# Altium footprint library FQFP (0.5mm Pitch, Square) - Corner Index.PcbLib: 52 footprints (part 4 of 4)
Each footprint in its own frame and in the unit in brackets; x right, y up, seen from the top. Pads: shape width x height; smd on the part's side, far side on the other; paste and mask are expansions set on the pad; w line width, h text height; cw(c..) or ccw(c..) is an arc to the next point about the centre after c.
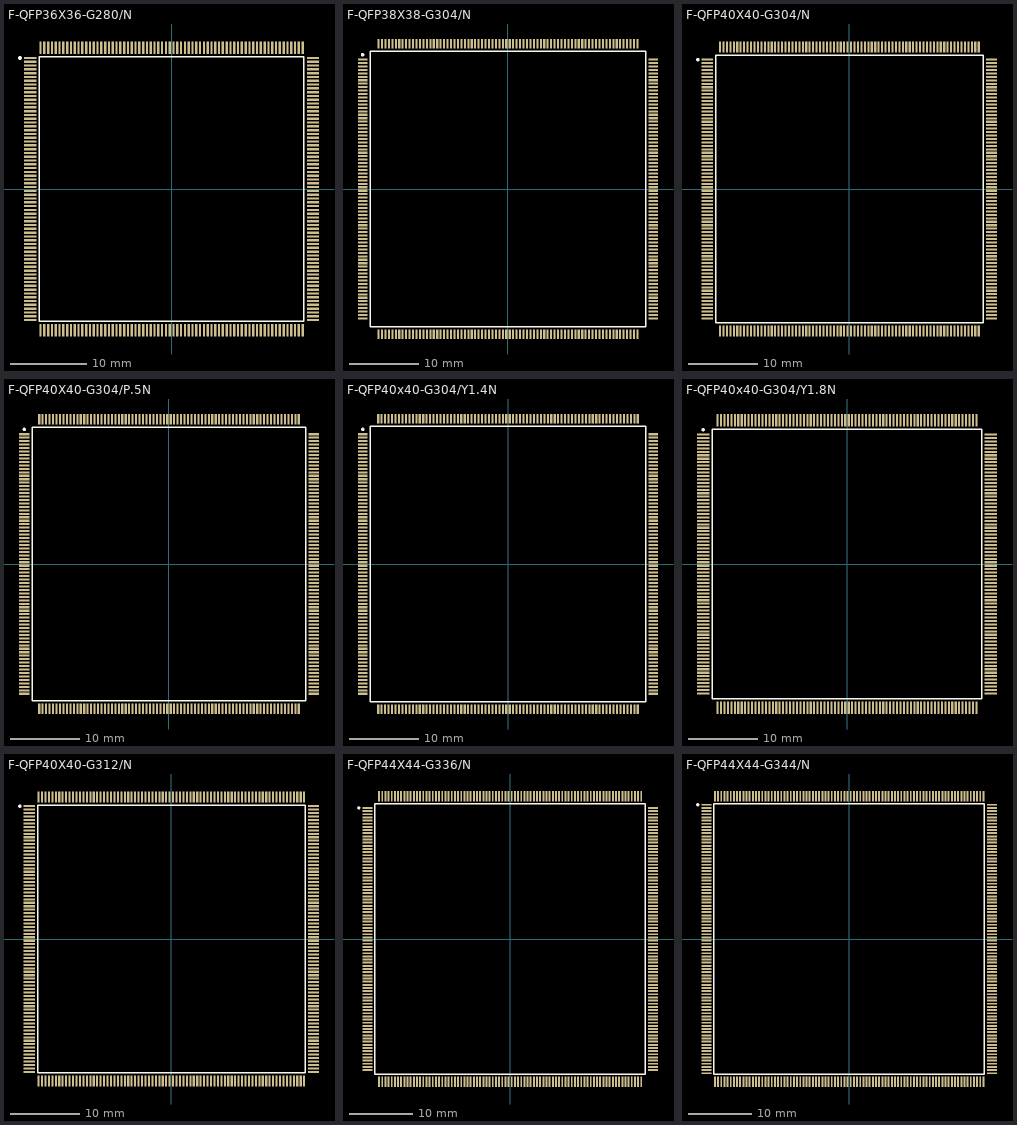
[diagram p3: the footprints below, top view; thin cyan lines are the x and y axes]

## F-QFP36X36-G280/N [mm]
pads (280):
  rect 1.6x0.3 smd: 1(-18.6,17.25) 2(-18.6,16.75) 3(-18.6,16.25) 4(-18.6,15.75) 5(-18.6,15.25) 6(-18.6,14.75) 7(-18.6,14.25) 8(-18.6,13.75) 9(-18.6,13.25) 10(-18.6,12.75) 11(-18.6,12.25) 12(-18.6,11.75) 13(-18.6,11.25) 14(-18.6,10.75) 15(-18.6,10.25) 16(-18.6,9.75) 17(-18.6,9.25) 18(-18.6,8.75) 19(-18.6,8.25) 20(-18.6,7.75) 21(-18.6,7.25) 22(-18.6,6.75) 23(-18.6,6.25) 24(-18.6,5.75) 25(-18.6,5.25) 26(-18.6,4.75) 27(-18.6,4.25) 28(-18.6,3.75) 29(-18.6,3.25) 30(-18.6,2.75) 31(-18.6,2.25) 32(-18.6,1.75) 33(-18.6,1.25) 34(-18.6,0.75) 35(-18.6,0.25) 36(-18.6,-0.25) 37(-18.6,-0.75) 38(-18.6,-1.25) 39(-18.6,-1.75) 40(-18.6,-2.25) 41(-18.6,-2.75) 42(-18.6,-3.25) 43(-18.6,-3.75) 44(-18.6,-4.25) 45(-18.6,-4.75) 46(-18.6,-5.25) 47(-18.6,-5.75) 48(-18.6,-6.25) 49(-18.6,-6.75) 50(-18.6,-7.25) 51(-18.6,-7.75) 52(-18.6,-8.25) 53(-18.6,-8.75) 54(-18.6,-9.25) 55(-18.6,-9.75) 56(-18.6,-10.25) 57(-18.6,-10.75) 58(-18.6,-11.25) 59(-18.6,-11.75) 60(-18.6,-12.25) 61(-18.6,-12.75) 62(-18.6,-13.25) 63(-18.6,-13.75) 64(-18.6,-14.25) 65(-18.6,-14.75) 66(-18.6,-15.25) 67(-18.6,-15.75) 68(-18.6,-16.25) 69(-18.6,-16.75) 70(-18.6,-17.25) 141(18.6,-17.25) 142(18.6,-16.75) 143(18.6,-16.25) 144(18.6,-15.75) 145(18.6,-15.25) 146(18.6,-14.75) 147(18.6,-14.25) 148(18.6,-13.75) 149(18.6,-13.25) 150(18.6,-12.75) 151(18.6,-12.25) 152(18.6,-11.75) 153(18.6,-11.25) 154(18.6,-10.75) 155(18.6,-10.25) 156(18.6,-9.75) 157(18.6,-9.25) 158(18.6,-8.75) 159(18.6,-8.25) 160(18.6,-7.75) 161(18.6,-7.25) 162(18.6,-6.75) 163(18.6,-6.25) 164(18.6,-5.75) 165(18.6,-5.25) 166(18.6,-4.75) 167(18.6,-4.25) 168(18.6,-3.75) 169(18.6,-3.25) 170(18.6,-2.75) 171(18.6,-2.25) 172(18.6,-1.75) 173(18.6,-1.25) 174(18.6,-0.75) 175(18.6,-0.25) 176(18.6,0.25) 177(18.6,0.75) 178(18.6,1.25) 179(18.6,1.75) 180(18.6,2.25) 181(18.6,2.75) 182(18.6,3.25) 183(18.6,3.75) 184(18.6,4.25) 185(18.6,4.75) 186(18.6,5.25) 187(18.6,5.75) 188(18.6,6.25) 189(18.6,6.75) 190(18.6,7.25) 191(18.6,7.75) 192(18.6,8.25) 193(18.6,8.75) 194(18.6,9.25) 195(18.6,9.75) 196(18.6,10.25) 197(18.6,10.75) 198(18.6,11.25) 199(18.6,11.75) 200(18.6,12.25) 201(18.6,12.75) 202(18.6,13.25) 203(18.6,13.75) 204(18.6,14.25) 205(18.6,14.75) 206(18.6,15.25) 207(18.6,15.75) 208(18.6,16.25) 209(18.6,16.75) 210(18.6,17.25)
  rect 0.3x1.6 smd: 71(-17.25,-18.6) 72(-16.75,-18.6) 73(-16.25,-18.6) 74(-15.75,-18.6) 75(-15.25,-18.6) 76(-14.75,-18.6) 77(-14.25,-18.6) 78(-13.75,-18.6) 79(-13.25,-18.6) 80(-12.75,-18.6) 81(-12.25,-18.6) 82(-11.75,-18.6) 83(-11.25,-18.6) 84(-10.75,-18.6) 85(-10.25,-18.6) 86(-9.75,-18.6) 87(-9.25,-18.6) 88(-8.75,-18.6) 89(-8.25,-18.6) 90(-7.75,-18.6) 91(-7.25,-18.6) 92(-6.75,-18.6) 93(-6.25,-18.6) 94(-5.75,-18.6) 95(-5.25,-18.6) 96(-4.75,-18.6) 97(-4.25,-18.6) 98(-3.75,-18.6) 99(-3.25,-18.6) 100(-2.75,-18.6) 101(-2.25,-18.6) 102(-1.75,-18.6) 103(-1.25,-18.6) 104(-0.75,-18.6) 105(-0.25,-18.6) 106(0.25,-18.6) 107(0.75,-18.6) 108(1.25,-18.6) 109(1.75,-18.6) 110(2.25,-18.6) 111(2.75,-18.6) 112(3.25,-18.6) 113(3.75,-18.6) 114(4.25,-18.6) 115(4.75,-18.6) 116(5.25,-18.6) 117(5.75,-18.6) 118(6.25,-18.6) 119(6.75,-18.6) 120(7.25,-18.6) 121(7.75,-18.6) 122(8.25,-18.6) 123(8.75,-18.6) 124(9.25,-18.6) 125(9.75,-18.6) 126(10.25,-18.6) 127(10.75,-18.6) 128(11.25,-18.6) 129(11.75,-18.6) 130(12.25,-18.6) 131(12.75,-18.6) 132(13.25,-18.6) 133(13.75,-18.6) 134(14.25,-18.6) 135(14.75,-18.6) 136(15.25,-18.6) 137(15.75,-18.6) 138(16.25,-18.6) 139(16.75,-18.6) 140(17.25,-18.6) 211(17.25,18.6) 212(16.75,18.6) 213(16.25,18.6) 214(15.75,18.6) 215(15.25,18.6) 216(14.75,18.6) 217(14.25,18.6) 218(13.75,18.6) 219(13.25,18.6) 220(12.75,18.6) 221(12.25,18.6) 222(11.75,18.6) 223(11.25,18.6) 224(10.75,18.6) 225(10.25,18.6) 226(9.75,18.6) 227(9.25,18.6) 228(8.75,18.6) 229(8.25,18.6) 230(7.75,18.6) 231(7.25,18.6) 232(6.75,18.6) 233(6.25,18.6) 234(5.75,18.6) 235(5.25,18.6) 236(4.75,18.6) 237(4.25,18.6) 238(3.75,18.6) 239(3.25,18.6) 240(2.75,18.6) 241(2.25,18.6) 242(1.75,18.6) 243(1.25,18.6) 244(0.75,18.6) 245(0.25,18.6) 246(-0.25,18.6) 247(-0.75,18.6) 248(-1.25,18.6) 249(-1.75,18.6) 250(-2.25,18.6) 251(-2.75,18.6) 252(-3.25,18.6) 253(-3.75,18.6) 254(-4.25,18.6) 255(-4.75,18.6) 256(-5.25,18.6) 257(-5.75,18.6) 258(-6.25,18.6) 259(-6.75,18.6) 260(-7.25,18.6) 261(-7.75,18.6) 262(-8.25,18.6) 263(-8.75,18.6) 264(-9.25,18.6) 265(-9.75,18.6) 266(-10.25,18.6) 267(-10.75,18.6) 268(-11.25,18.6) 269(-11.75,18.6) 270(-12.25,18.6) 271(-12.75,18.6) 272(-13.25,18.6) 273(-13.75,18.6) 274(-14.25,18.6) 275(-14.75,18.6) 276(-15.25,18.6) 277(-15.75,18.6) 278(-16.25,18.6) 279(-16.75,18.6) 280(-17.25,18.6)
Top Overlay:
  circle w0.25: c-19.96,17.25 r0.125
  lines w0.2: -17.4,-17.4 17.4,-17.4 17.4,17.4 -17.4,17.4 -17.4,-17.4

## F-QFP38X38-G304/N [mm]
pads (304):
  rect 1.35x0.3 smd: 1(-21.05,18.75) 2(-21.05,18.25) 3(-21.05,17.75) 4(-21.05,17.25) 5(-21.05,16.75) 6(-21.05,16.25) 7(-21.05,15.75) 8(-21.05,15.25) 9(-21.05,14.75) 10(-21.05,14.25) 11(-21.05,13.75) 12(-21.05,13.25) 13(-21.05,12.75) 14(-21.05,12.25) 15(-21.05,11.75) 16(-21.05,11.25) 17(-21.05,10.75) 18(-21.05,10.25) 19(-21.05,9.75) 20(-21.05,9.25) 21(-21.05,8.75) 22(-21.05,8.25) 23(-21.05,7.75) 24(-21.05,7.25) 25(-21.05,6.75) 26(-21.05,6.25) 27(-21.05,5.75) 28(-21.05,5.25) 29(-21.05,4.75) 30(-21.05,4.25) 31(-21.05,3.75) 32(-21.05,3.25) 33(-21.05,2.75) 34(-21.05,2.25) 35(-21.05,1.75) 36(-21.05,1.25) 37(-21.05,0.75) 38(-21.05,0.25) 39(-21.05,-0.25) 40(-21.05,-0.75) 41(-21.05,-1.25) 42(-21.05,-1.75) 43(-21.05,-2.25) 44(-21.05,-2.75) 45(-21.05,-3.25) 46(-21.05,-3.75) 47(-21.05,-4.25) 48(-21.05,-4.75) 49(-21.05,-5.25) 50(-21.05,-5.75) 51(-21.05,-6.25) 52(-21.05,-6.75) 53(-21.05,-7.25) 54(-21.05,-7.75) 55(-21.05,-8.25) 56(-21.05,-8.75) 57(-21.05,-9.25) 58(-21.05,-9.75) 59(-21.05,-10.25) 60(-21.05,-10.75) 61(-21.05,-11.25) 62(-21.05,-11.75) 63(-21.05,-12.25) 64(-21.05,-12.75) 65(-21.05,-13.25) 66(-21.05,-13.75) 67(-21.05,-14.25) 68(-21.05,-14.75) 69(-21.05,-15.25) 70(-21.05,-15.75) 71(-21.05,-16.25) 72(-21.05,-16.75) 73(-21.05,-17.25) 74(-21.05,-17.75) 75(-21.05,-18.25) 76(-21.05,-18.75) 153(21.05,-18.75) 154(21.05,-18.25) 155(21.05,-17.75) 156(21.05,-17.25) 157(21.05,-16.75) 158(21.05,-16.25) 159(21.05,-15.75) 160(21.05,-15.25) 161(21.05,-14.75) 162(21.05,-14.25) 163(21.05,-13.75) 164(21.05,-13.25) 165(21.05,-12.75) 166(21.05,-12.25) 167(21.05,-11.75) 168(21.05,-11.25) 169(21.05,-10.75) 170(21.05,-10.25) 171(21.05,-9.75) 172(21.05,-9.25) 173(21.05,-8.75) 174(21.05,-8.25) 175(21.05,-7.75) 176(21.05,-7.25) 177(21.05,-6.75) 178(21.05,-6.25) 179(21.05,-5.75) 180(21.05,-5.25) 181(21.05,-4.75) 182(21.05,-4.25) 183(21.05,-3.75) 184(21.05,-3.25) 185(21.05,-2.75) 186(21.05,-2.25) 187(21.05,-1.75) 188(21.05,-1.25) 189(21.05,-0.75) 190(21.05,-0.25) 191(21.05,0.25) 192(21.05,0.75) 193(21.05,1.25) 194(21.05,1.75) 195(21.05,2.25) 196(21.05,2.75) 197(21.05,3.25) 198(21.05,3.75) 199(21.05,4.25) 200(21.05,4.75) 201(21.05,5.25) 202(21.05,5.75) 203(21.05,6.25) 204(21.05,6.75) 205(21.05,7.25) 206(21.05,7.75) 207(21.05,8.25) 208(21.05,8.75) 209(21.05,9.25) 210(21.05,9.75) 211(21.05,10.25) 212(21.05,10.75) 213(21.05,11.25) 214(21.05,11.75) 215(21.05,12.25) 216(21.05,12.75) 217(21.05,13.25) 218(21.05,13.75) 219(21.05,14.25) 220(21.05,14.75) 221(21.05,15.25) 222(21.05,15.75) 223(21.05,16.25) 224(21.05,16.75) 225(21.05,17.25) 226(21.05,17.75) 227(21.05,18.25) 228(21.05,18.75)
  rect 0.3x1.35 smd: 77(-18.75,-21.05) 78(-18.25,-21.05) 79(-17.75,-21.05) 80(-17.25,-21.05) 81(-16.75,-21.05) 82(-16.25,-21.05) 83(-15.75,-21.05) 84(-15.25,-21.05) 85(-14.75,-21.05) 86(-14.25,-21.05) 87(-13.75,-21.05) 88(-13.25,-21.05) 89(-12.75,-21.05) 90(-12.25,-21.05) 91(-11.75,-21.05) 92(-11.25,-21.05) 93(-10.75,-21.05) 94(-10.25,-21.05) 95(-9.75,-21.05) 96(-9.25,-21.05) 97(-8.75,-21.05) 98(-8.25,-21.05) 99(-7.75,-21.05) 100(-7.25,-21.05) 101(-6.75,-21.05) 102(-6.25,-21.05) 103(-5.75,-21.05) 104(-5.25,-21.05) 105(-4.75,-21.05) 106(-4.25,-21.05) 107(-3.75,-21.05) 108(-3.25,-21.05) 109(-2.75,-21.05) 110(-2.25,-21.05) 111(-1.75,-21.05) 112(-1.25,-21.05) 113(-0.75,-21.05) 114(-0.25,-21.05) 115(0.25,-21.05) 116(0.75,-21.05) 117(1.25,-21.05) 118(1.75,-21.05) 119(2.25,-21.05) 120(2.75,-21.05) 121(3.25,-21.05) 122(3.75,-21.05) 123(4.25,-21.05) 124(4.75,-21.05) 125(5.25,-21.05) 126(5.75,-21.05) 127(6.25,-21.05) 128(6.75,-21.05) 129(7.25,-21.05) 130(7.75,-21.05) 131(8.25,-21.05) 132(8.75,-21.05) 133(9.25,-21.05) 134(9.75,-21.05) 135(10.25,-21.05) 136(10.75,-21.05) 137(11.25,-21.05) 138(11.75,-21.05) 139(12.25,-21.05) 140(12.75,-21.05) 141(13.25,-21.05) 142(13.75,-21.05) 143(14.25,-21.05) 144(14.75,-21.05) 145(15.25,-21.05) 146(15.75,-21.05) 147(16.25,-21.05) 148(16.75,-21.05) 149(17.25,-21.05) 150(17.75,-21.05) 151(18.25,-21.05) 152(18.75,-21.05) 229(18.75,21.05) 230(18.25,21.05) 231(17.75,21.05) 232(17.25,21.05) 233(16.75,21.05) 234(16.25,21.05) 235(15.75,21.05) 236(15.25,21.05) 237(14.75,21.05) 238(14.25,21.05) 239(13.75,21.05) 240(13.25,21.05) 241(12.75,21.05) 242(12.25,21.05) 243(11.75,21.05) 244(11.25,21.05) 245(10.75,21.05) 246(10.25,21.05) 247(9.75,21.05) 248(9.25,21.05) 249(8.75,21.05) 250(8.25,21.05) 251(7.75,21.05) 252(7.25,21.05) 253(6.75,21.05) 254(6.25,21.05) 255(5.75,21.05) 256(5.25,21.05) 257(4.75,21.05) 258(4.25,21.05) 259(3.75,21.05) 260(3.25,21.05) 261(2.75,21.05) 262(2.25,21.05) 263(1.75,21.05) 264(1.25,21.05) 265(0.75,21.05) 266(0.25,21.05) 267(-0.25,21.05) 268(-0.75,21.05) 269(-1.25,21.05) 270(-1.75,21.05) 271(-2.25,21.05) 272(-2.75,21.05) 273(-3.25,21.05) 274(-3.75,21.05) 275(-4.25,21.05) 276(-4.75,21.05) 277(-5.25,21.05) 278(-5.75,21.05) 279(-6.25,21.05) 280(-6.75,21.05) 281(-7.25,21.05) 282(-7.75,21.05) 283(-8.25,21.05) 284(-8.75,21.05) 285(-9.25,21.05) 286(-9.75,21.05) 287(-10.25,21.05) 288(-10.75,21.05) 289(-11.25,21.05) 290(-11.75,21.05) 291(-12.25,21.05) 292(-12.75,21.05) 293(-13.25,21.05) 294(-13.75,21.05) 295(-14.25,21.05) 296(-14.75,21.05) 297(-15.25,21.05) 298(-15.75,21.05) 299(-16.25,21.05) 300(-16.75,21.05) 301(-17.25,21.05) 302(-17.75,21.05) 303(-18.25,21.05) 304(-18.75,21.05)
Top Overlay:
  circle w0.25: c-21.05,19.45 r0.125
  lines w0.2: -19.975,-19.975 -19.975,19.975 19.975,19.975 19.975,-19.975 -19.975,-19.975

## F-QFP40X40-G304/N [mm]
pads (304):
  rect 1.6x0.3 smd: 1(-20.6,18.75) 2(-20.6,18.25) 3(-20.6,17.75) 4(-20.6,17.25) 5(-20.6,16.75) 6(-20.6,16.25) 7(-20.6,15.75) 8(-20.6,15.25) 9(-20.6,14.75) 10(-20.6,14.25) 11(-20.6,13.75) 12(-20.6,13.25) 13(-20.6,12.75) 14(-20.6,12.25) 15(-20.6,11.75) 16(-20.6,11.25) 17(-20.6,10.75) 18(-20.6,10.25) 19(-20.6,9.75) 20(-20.6,9.25) 21(-20.6,8.75) 22(-20.6,8.25) 23(-20.6,7.75) 24(-20.6,7.25) 25(-20.6,6.75) 26(-20.6,6.25) 27(-20.6,5.75) 28(-20.6,5.25) 29(-20.6,4.75) 30(-20.6,4.25) 31(-20.6,3.75) 32(-20.6,3.25) 33(-20.6,2.75) 34(-20.6,2.25) 35(-20.6,1.75) 36(-20.6,1.25) 37(-20.6,0.75) 38(-20.6,0.25) 39(-20.6,-0.25) 40(-20.6,-0.75) 41(-20.6,-1.25) 42(-20.6,-1.75) 43(-20.6,-2.25) 44(-20.6,-2.75) 45(-20.6,-3.25) 46(-20.6,-3.75) 47(-20.6,-4.25) 48(-20.6,-4.75) 49(-20.6,-5.25) 50(-20.6,-5.75) 51(-20.6,-6.25) 52(-20.6,-6.75) 53(-20.6,-7.25) 54(-20.6,-7.75) 55(-20.6,-8.25) 56(-20.6,-8.75) 57(-20.6,-9.25) 58(-20.6,-9.75) 59(-20.6,-10.25) 60(-20.6,-10.75) 61(-20.6,-11.25) 62(-20.6,-11.75) 63(-20.6,-12.25) 64(-20.6,-12.75) 65(-20.6,-13.25) 66(-20.6,-13.75) 67(-20.6,-14.25) 68(-20.6,-14.75) 69(-20.6,-15.25) 70(-20.6,-15.75) 71(-20.6,-16.25) 72(-20.6,-16.75) 73(-20.6,-17.25) 74(-20.6,-17.75) 75(-20.6,-18.25) 76(-20.6,-18.75) 153(20.6,-18.75) 154(20.6,-18.25) 155(20.6,-17.75) 156(20.6,-17.25) 157(20.6,-16.75) 158(20.6,-16.25) 159(20.6,-15.75) 160(20.6,-15.25) 161(20.6,-14.75) 162(20.6,-14.25) 163(20.6,-13.75) 164(20.6,-13.25) 165(20.6,-12.75) 166(20.6,-12.25) 167(20.6,-11.75) 168(20.6,-11.25) 169(20.6,-10.75) 170(20.6,-10.25) 171(20.6,-9.75) 172(20.6,-9.25) 173(20.6,-8.75) 174(20.6,-8.25) 175(20.6,-7.75) 176(20.6,-7.25) 177(20.6,-6.75) 178(20.6,-6.25) 179(20.6,-5.75) 180(20.6,-5.25) 181(20.6,-4.75) 182(20.6,-4.25) 183(20.6,-3.75) 184(20.6,-3.25) 185(20.6,-2.75) 186(20.6,-2.25) 187(20.6,-1.75) 188(20.6,-1.25) 189(20.6,-0.75) 190(20.6,-0.25) 191(20.6,0.25) 192(20.6,0.75) 193(20.6,1.25) 194(20.6,1.75) 195(20.6,2.25) 196(20.6,2.75) 197(20.6,3.25) 198(20.6,3.75) 199(20.6,4.25) 200(20.6,4.75) 201(20.6,5.25) 202(20.6,5.75) 203(20.6,6.25) 204(20.6,6.75) 205(20.6,7.25) 206(20.6,7.75) 207(20.6,8.25) 208(20.6,8.75) 209(20.6,9.25) 210(20.6,9.75) 211(20.6,10.25) 212(20.6,10.75) 213(20.6,11.25) 214(20.6,11.75) 215(20.6,12.25) 216(20.6,12.75) 217(20.6,13.25) 218(20.6,13.75) 219(20.6,14.25) 220(20.6,14.75) 221(20.6,15.25) 222(20.6,15.75) 223(20.6,16.25) 224(20.6,16.75) 225(20.6,17.25) 226(20.6,17.75) 227(20.6,18.25) 228(20.6,18.75)
  rect 0.3x1.6 smd: 77(-18.75,-20.6) 78(-18.25,-20.6) 79(-17.75,-20.6) 80(-17.25,-20.6) 81(-16.75,-20.6) 82(-16.25,-20.6) 83(-15.75,-20.6) 84(-15.25,-20.6) 85(-14.75,-20.6) 86(-14.25,-20.6) 87(-13.75,-20.6) 88(-13.25,-20.6) 89(-12.75,-20.6) 90(-12.25,-20.6) 91(-11.75,-20.6) 92(-11.25,-20.6) 93(-10.75,-20.6) 94(-10.25,-20.6) 95(-9.75,-20.6) 96(-9.25,-20.6) 97(-8.75,-20.6) 98(-8.25,-20.6) 99(-7.75,-20.6) 100(-7.25,-20.6) 101(-6.75,-20.6) 102(-6.25,-20.6) 103(-5.75,-20.6) 104(-5.25,-20.6) 105(-4.75,-20.6) 106(-4.25,-20.6) 107(-3.75,-20.6) 108(-3.25,-20.6) 109(-2.75,-20.6) 110(-2.25,-20.6) 111(-1.75,-20.6) 112(-1.25,-20.6) 113(-0.75,-20.6) 114(-0.25,-20.6) 115(0.25,-20.6) 116(0.75,-20.6) 117(1.25,-20.6) 118(1.75,-20.6) 119(2.25,-20.6) 120(2.75,-20.6) 121(3.25,-20.6) 122(3.75,-20.6) 123(4.25,-20.6) 124(4.75,-20.6) 125(5.25,-20.6) 126(5.75,-20.6) 127(6.25,-20.6) 128(6.75,-20.6) 129(7.25,-20.6) 130(7.75,-20.6) 131(8.25,-20.6) 132(8.75,-20.6) 133(9.25,-20.6) 134(9.75,-20.6) 135(10.25,-20.6) 136(10.75,-20.6) 137(11.25,-20.6) 138(11.75,-20.6) 139(12.25,-20.6) 140(12.75,-20.6) 141(13.25,-20.6) 142(13.75,-20.6) 143(14.25,-20.6) 144(14.75,-20.6) 145(15.25,-20.6) 146(15.75,-20.6) 147(16.25,-20.6) 148(16.75,-20.6) 149(17.25,-20.6) 150(17.75,-20.6) 151(18.25,-20.6) 152(18.75,-20.6) 229(18.75,20.6) 230(18.25,20.6) 231(17.75,20.6) 232(17.25,20.6) 233(16.75,20.6) 234(16.25,20.6) 235(15.75,20.6) 236(15.25,20.6) 237(14.75,20.6) 238(14.25,20.6) 239(13.75,20.6) 240(13.25,20.6) 241(12.75,20.6) 242(12.25,20.6) 243(11.75,20.6) 244(11.25,20.6) 245(10.75,20.6) 246(10.25,20.6) 247(9.75,20.6) 248(9.25,20.6) 249(8.75,20.6) 250(8.25,20.6) 251(7.75,20.6) 252(7.25,20.6) 253(6.75,20.6) 254(6.25,20.6) 255(5.75,20.6) 256(5.25,20.6) 257(4.75,20.6) 258(4.25,20.6) 259(3.75,20.6) 260(3.25,20.6) 261(2.75,20.6) 262(2.25,20.6) 263(1.75,20.6) 264(1.25,20.6) 265(0.75,20.6) 266(0.25,20.6) 267(-0.25,20.6) 268(-0.75,20.6) 269(-1.25,20.6) 270(-1.75,20.6) 271(-2.25,20.6) 272(-2.75,20.6) 273(-3.25,20.6) 274(-3.75,20.6) 275(-4.25,20.6) 276(-4.75,20.6) 277(-5.25,20.6) 278(-5.75,20.6) 279(-6.25,20.6) 280(-6.75,20.6) 281(-7.25,20.6) 282(-7.75,20.6) 283(-8.25,20.6) 284(-8.75,20.6) 285(-9.25,20.6) 286(-9.75,20.6) 287(-10.25,20.6) 288(-10.75,20.6) 289(-11.25,20.6) 290(-11.75,20.6) 291(-12.25,20.6) 292(-12.75,20.6) 293(-13.25,20.6) 294(-13.75,20.6) 295(-14.25,20.6) 296(-14.75,20.6) 297(-15.25,20.6) 298(-15.75,20.6) 299(-16.25,20.6) 300(-16.75,20.6) 301(-17.25,20.6) 302(-17.75,20.6) 303(-18.25,20.6) 304(-18.75,20.6)
Top Overlay:
  circle w0.25: c-21.96,18.75 r0.125
  lines w0.2: -19.4,-19.4 -19.4,19.4 19.4,19.4 19.4,-19.4 -19.4,-19.4

## F-QFP40X40-G304/P.5N [mm]
pads (304):
  rect 1.55x0.3 smd: 1(-20.9,18.75) 2(-20.9,18.25) 3(-20.9,17.75) 4(-20.9,17.25) 5(-20.9,16.75) 6(-20.9,16.25) 7(-20.9,15.75) 8(-20.9,15.25) 9(-20.9,14.75) 10(-20.9,14.25) 11(-20.9,13.75) 12(-20.9,13.25) 13(-20.9,12.75) 14(-20.9,12.25) 15(-20.9,11.75) 16(-20.9,11.25) 17(-20.9,10.75) 18(-20.9,10.25) 19(-20.9,9.75) 20(-20.9,9.25) 21(-20.9,8.75) 22(-20.9,8.25) 23(-20.9,7.75) 24(-20.9,7.25) 25(-20.9,6.75) 26(-20.9,6.25) 27(-20.9,5.75) 28(-20.9,5.25) 29(-20.9,4.75) 30(-20.9,4.25) 31(-20.9,3.75) 32(-20.9,3.25) 33(-20.9,2.75) 34(-20.9,2.25) 35(-20.9,1.75) 36(-20.9,1.25) 37(-20.9,0.75) 38(-20.9,0.25) 39(-20.9,-0.25) 40(-20.9,-0.75) 41(-20.9,-1.25) 42(-20.9,-1.75) 43(-20.9,-2.25) 44(-20.9,-2.75) 45(-20.9,-3.25) 46(-20.9,-3.75) 47(-20.9,-4.25) 48(-20.9,-4.75) 49(-20.9,-5.25) 50(-20.9,-5.75) 51(-20.9,-6.25) 52(-20.9,-6.75) 53(-20.9,-7.25) 54(-20.9,-7.75) 55(-20.9,-8.25) 56(-20.9,-8.75) 57(-20.9,-9.25) 58(-20.9,-9.75) 59(-20.9,-10.25) 60(-20.9,-10.75) 61(-20.9,-11.25) 62(-20.9,-11.75) 63(-20.9,-12.25) 64(-20.9,-12.75) 65(-20.9,-13.25) 66(-20.9,-13.75) 67(-20.9,-14.25) 68(-20.9,-14.75) 69(-20.9,-15.25) 70(-20.9,-15.75) 71(-20.9,-16.25) 72(-20.9,-16.75) 73(-20.9,-17.25) 74(-20.9,-17.75) 75(-20.9,-18.25) 76(-20.9,-18.75) 153(20.9,-18.75) 154(20.9,-18.25) 155(20.9,-17.75) 156(20.9,-17.25) 157(20.9,-16.75) 158(20.9,-16.25) 159(20.9,-15.75) 160(20.9,-15.25) 161(20.9,-14.75) 162(20.9,-14.25) 163(20.9,-13.75) 164(20.9,-13.25) 165(20.9,-12.75) 166(20.9,-12.25) 167(20.9,-11.75) 168(20.9,-11.25) 169(20.9,-10.75) 170(20.9,-10.25) 171(20.9,-9.75) 172(20.9,-9.25) 173(20.9,-8.75) 174(20.9,-8.25) 175(20.9,-7.75) 176(20.9,-7.25) 177(20.9,-6.75) 178(20.9,-6.25) 179(20.9,-5.75) 180(20.9,-5.25) 181(20.9,-4.75) 182(20.9,-4.25) 183(20.9,-3.75) 184(20.9,-3.25) 185(20.9,-2.75) 186(20.9,-2.25) 187(20.9,-1.75) 188(20.9,-1.25) 189(20.9,-0.75) 190(20.9,-0.25) 191(20.9,0.25) 192(20.9,0.75) 193(20.9,1.25) 194(20.9,1.75) 195(20.9,2.25) 196(20.9,2.75) 197(20.9,3.25) 198(20.9,3.75) 199(20.9,4.25) 200(20.9,4.75) 201(20.9,5.25) 202(20.9,5.75) 203(20.9,6.25) 204(20.9,6.75) 205(20.9,7.25) 206(20.9,7.75) 207(20.9,8.25) 208(20.9,8.75) 209(20.9,9.25) 210(20.9,9.75) 211(20.9,10.25) 212(20.9,10.75) 213(20.9,11.25) 214(20.9,11.75) 215(20.9,12.25) 216(20.9,12.75) 217(20.9,13.25) 218(20.9,13.75) 219(20.9,14.25) 220(20.9,14.75) 221(20.9,15.25) 222(20.9,15.75) 223(20.9,16.25) 224(20.9,16.75) 225(20.9,17.25) 226(20.9,17.75) 227(20.9,18.25) 228(20.9,18.75)
  rect 0.3x1.55 smd: 77(-18.75,-20.9) 78(-18.25,-20.9) 79(-17.75,-20.9) 80(-17.25,-20.9) 81(-16.75,-20.9) 82(-16.25,-20.9) 83(-15.75,-20.9) 84(-15.25,-20.9) 85(-14.75,-20.9) 86(-14.25,-20.9) 87(-13.75,-20.9) 88(-13.25,-20.9) 89(-12.75,-20.9) 90(-12.25,-20.9) 91(-11.75,-20.9) 92(-11.25,-20.9) 93(-10.75,-20.9) 94(-10.25,-20.9) 95(-9.75,-20.9) 96(-9.25,-20.9) 97(-8.75,-20.9) 98(-8.25,-20.9) 99(-7.75,-20.9) 100(-7.25,-20.9) 101(-6.75,-20.9) 102(-6.25,-20.9) 103(-5.75,-20.9) 104(-5.25,-20.9) 105(-4.75,-20.9) 106(-4.25,-20.9) 107(-3.75,-20.9) 108(-3.25,-20.9) 109(-2.75,-20.9) 110(-2.25,-20.9) 111(-1.75,-20.9) 112(-1.25,-20.9) 113(-0.75,-20.9) 114(-0.25,-20.9) 115(0.25,-20.9) 116(0.75,-20.9) 117(1.25,-20.9) 118(1.75,-20.9) 119(2.25,-20.9) 120(2.75,-20.9) 121(3.25,-20.9) 122(3.75,-20.9) 123(4.25,-20.9) 124(4.75,-20.9) 125(5.25,-20.9) 126(5.75,-20.9) 127(6.25,-20.9) 128(6.75,-20.9) 129(7.25,-20.9) 130(7.75,-20.9) 131(8.25,-20.9) 132(8.75,-20.9) 133(9.25,-20.9) 134(9.75,-20.9) 135(10.25,-20.9) 136(10.75,-20.9) 137(11.25,-20.9) 138(11.75,-20.9) 139(12.25,-20.9) 140(12.75,-20.9) 141(13.25,-20.9) 142(13.75,-20.9) 143(14.25,-20.9) 144(14.75,-20.9) 145(15.25,-20.9) 146(15.75,-20.9) 147(16.25,-20.9) 148(16.75,-20.9) 149(17.25,-20.9) 150(17.75,-20.9) 151(18.25,-20.9) 152(18.75,-20.9) 229(18.75,20.9) 230(18.25,20.9) 231(17.75,20.9) 232(17.25,20.9) 233(16.75,20.9) 234(16.25,20.9) 235(15.75,20.9) 236(15.25,20.9) 237(14.75,20.9) 238(14.25,20.9) 239(13.75,20.9) 240(13.25,20.9) 241(12.75,20.9) 242(12.25,20.9) 243(11.75,20.9) 244(11.25,20.9) 245(10.75,20.9) 246(10.25,20.9) 247(9.75,20.9) 248(9.25,20.9) 249(8.75,20.9) 250(8.25,20.9) 251(7.75,20.9) 252(7.25,20.9) 253(6.75,20.9) 254(6.25,20.9) 255(5.75,20.9) 256(5.25,20.9) 257(4.75,20.9) 258(4.25,20.9) 259(3.75,20.9) 260(3.25,20.9) 261(2.75,20.9) 262(2.25,20.9) 263(1.75,20.9) 264(1.25,20.9) 265(0.75,20.9) 266(0.25,20.9) 267(-0.25,20.9) 268(-0.75,20.9) 269(-1.25,20.9) 270(-1.75,20.9) 271(-2.25,20.9) 272(-2.75,20.9) 273(-3.25,20.9) 274(-3.75,20.9) 275(-4.25,20.9) 276(-4.75,20.9) 277(-5.25,20.9) 278(-5.75,20.9) 279(-6.25,20.9) 280(-6.75,20.9) 281(-7.25,20.9) 282(-7.75,20.9) 283(-8.25,20.9) 284(-8.75,20.9) 285(-9.25,20.9) 286(-9.75,20.9) 287(-10.25,20.9) 288(-10.75,20.9) 289(-11.25,20.9) 290(-11.75,20.9) 291(-12.25,20.9) 292(-12.75,20.9) 293(-13.25,20.9) 294(-13.75,20.9) 295(-14.25,20.9) 296(-14.75,20.9) 297(-15.25,20.9) 298(-15.75,20.9) 299(-16.25,20.9) 300(-16.75,20.9) 301(-17.25,20.9) 302(-17.75,20.9) 303(-18.25,20.9) 304(-18.75,20.9)
Top Overlay:
  circle w0.25: c-20.9,19.45 r0.125
  lines w0.2: -19.725,-19.725 19.725,-19.725 19.725,19.725 -19.725,19.725 -19.725,-19.725

## F-QFP40x40-G304/Y1.4N [mm]
pads (304):
  rect 1.4x0.3 smd: 1(-20.975,18.75) 2(-20.975,18.25) 3(-20.975,17.75) 4(-20.975,17.25) 5(-20.975,16.75) 6(-20.975,16.25) 7(-20.975,15.75) 8(-20.975,15.25) 9(-20.975,14.75) 10(-20.975,14.25) 11(-20.975,13.75) 12(-20.975,13.25) 13(-20.975,12.75) 14(-20.975,12.25) 15(-20.975,11.75) 16(-20.975,11.25) 17(-20.975,10.75) 18(-20.975,10.25) 19(-20.975,9.75) 20(-20.975,9.25) 21(-20.975,8.75) 22(-20.975,8.25) 23(-20.975,7.75) 24(-20.975,7.25) 25(-20.975,6.75) 26(-20.975,6.25) 27(-20.975,5.75) 28(-20.975,5.25) 29(-20.975,4.75) 30(-20.975,4.25) 31(-20.975,3.75) 32(-20.975,3.25) 33(-20.975,2.75) 34(-20.975,2.25) 35(-20.975,1.75) 36(-20.975,1.25) 37(-20.975,0.75) 38(-20.975,0.25) 39(-20.975,-0.25) 40(-20.975,-0.75) 41(-20.975,-1.25) 42(-20.975,-1.75) 43(-20.975,-2.25) 44(-20.975,-2.75) 45(-20.975,-3.25) 46(-20.975,-3.75) 47(-20.975,-4.25) 48(-20.975,-4.75) 49(-20.975,-5.25) 50(-20.975,-5.75) 51(-20.975,-6.25) 52(-20.975,-6.75) 53(-20.975,-7.25) 54(-20.975,-7.75) 55(-20.975,-8.25) 56(-20.975,-8.75) 57(-20.975,-9.25) 58(-20.975,-9.75) 59(-20.975,-10.25) 60(-20.975,-10.75) 61(-20.975,-11.25) 62(-20.975,-11.75) 63(-20.975,-12.25) 64(-20.975,-12.75) 65(-20.975,-13.25) 66(-20.975,-13.75) 67(-20.975,-14.25) 68(-20.975,-14.75) 69(-20.975,-15.25) 70(-20.975,-15.75) 71(-20.975,-16.25) 72(-20.975,-16.75) 73(-20.975,-17.25) 74(-20.975,-17.75) 75(-20.975,-18.25) 76(-20.975,-18.75) 153(20.975,-18.75) 154(20.975,-18.25) 155(20.975,-17.75) 156(20.975,-17.25) 157(20.975,-16.75) 158(20.975,-16.25) 159(20.975,-15.75) 160(20.975,-15.25) 161(20.975,-14.75) 162(20.975,-14.25) 163(20.975,-13.75) 164(20.975,-13.25) 165(20.975,-12.75) 166(20.975,-12.25) 167(20.975,-11.75) 168(20.975,-11.25) 169(20.975,-10.75) 170(20.975,-10.25) 171(20.975,-9.75) 172(20.975,-9.25) 173(20.975,-8.75) 174(20.975,-8.25) 175(20.975,-7.75) 176(20.975,-7.25) 177(20.975,-6.75) 178(20.975,-6.25) 179(20.975,-5.75) 180(20.975,-5.25) 181(20.975,-4.75) 182(20.975,-4.25) 183(20.975,-3.75) 184(20.975,-3.25) 185(20.975,-2.75) 186(20.975,-2.25) 187(20.975,-1.75) 188(20.975,-1.25) 189(20.975,-0.75) 190(20.975,-0.25) 191(20.975,0.25) 192(20.975,0.75) 193(20.975,1.25) 194(20.975,1.75) 195(20.975,2.25) 196(20.975,2.75) 197(20.975,3.25) 198(20.975,3.75) 199(20.975,4.25) 200(20.975,4.75) 201(20.975,5.25) 202(20.975,5.75) 203(20.975,6.25) 204(20.975,6.75) 205(20.975,7.25) 206(20.975,7.75) 207(20.975,8.25) 208(20.975,8.75) 209(20.975,9.25) 210(20.975,9.75) 211(20.975,10.25) 212(20.975,10.75) 213(20.975,11.25) 214(20.975,11.75) 215(20.975,12.25) 216(20.975,12.75) 217(20.975,13.25) 218(20.975,13.75) 219(20.975,14.25) 220(20.975,14.75) 221(20.975,15.25) 222(20.975,15.75) 223(20.975,16.25) 224(20.975,16.75) 225(20.975,17.25) 226(20.975,17.75) 227(20.975,18.25) 228(20.975,18.75)
  rect 0.3x1.4 smd: 77(-18.75,-20.975) 78(-18.25,-20.975) 79(-17.75,-20.975) 80(-17.25,-20.975) 81(-16.75,-20.975) 82(-16.25,-20.975) 83(-15.75,-20.975) 84(-15.25,-20.975) 85(-14.75,-20.975) 86(-14.25,-20.975) 87(-13.75,-20.975) 88(-13.25,-20.975) 89(-12.75,-20.975) 90(-12.25,-20.975) 91(-11.75,-20.975) 92(-11.25,-20.975) 93(-10.75,-20.975) 94(-10.25,-20.975) 95(-9.75,-20.975) 96(-9.25,-20.975) 97(-8.75,-20.975) 98(-8.25,-20.975) 99(-7.75,-20.975) 100(-7.25,-20.975) 101(-6.75,-20.975) 102(-6.25,-20.975) 103(-5.75,-20.975) 104(-5.25,-20.975) 105(-4.75,-20.975) 106(-4.25,-20.975) 107(-3.75,-20.975) 108(-3.25,-20.975) 109(-2.75,-20.975) 110(-2.25,-20.975) 111(-1.75,-20.975) 112(-1.25,-20.975) 113(-0.75,-20.975) 114(-0.25,-20.975) 115(0.25,-20.975) 116(0.75,-20.975) 117(1.25,-20.975) 118(1.75,-20.975) 119(2.25,-20.975) 120(2.75,-20.975) 121(3.25,-20.975) 122(3.75,-20.975) 123(4.25,-20.975) 124(4.75,-20.975) 125(5.25,-20.975) 126(5.75,-20.975) 127(6.25,-20.975) 128(6.75,-20.975) 129(7.25,-20.975) 130(7.75,-20.975) 131(8.25,-20.975) 132(8.75,-20.975) 133(9.25,-20.975) 134(9.75,-20.975) 135(10.25,-20.975) 136(10.75,-20.975) 137(11.25,-20.975) 138(11.75,-20.975) 139(12.25,-20.975) 140(12.75,-20.975) 141(13.25,-20.975) 142(13.75,-20.975) 143(14.25,-20.975) 144(14.75,-20.975) 145(15.25,-20.975) 146(15.75,-20.975) 147(16.25,-20.975) 148(16.75,-20.975) 149(17.25,-20.975) 150(17.75,-20.975) 151(18.25,-20.975) 152(18.75,-20.975) 229(18.75,20.975) 230(18.25,20.975) 231(17.75,20.975) 232(17.25,20.975) 233(16.75,20.975) 234(16.25,20.975) 235(15.75,20.975) 236(15.25,20.975) 237(14.75,20.975) 238(14.25,20.975) 239(13.75,20.975) 240(13.25,20.975) 241(12.75,20.975) 242(12.25,20.975) 243(11.75,20.975) 244(11.25,20.975) 245(10.75,20.975) 246(10.25,20.975) 247(9.75,20.975) 248(9.25,20.975) 249(8.75,20.975) 250(8.25,20.975) 251(7.75,20.975) 252(7.25,20.975) 253(6.75,20.975) 254(6.25,20.975) 255(5.75,20.975) 256(5.25,20.975) 257(4.75,20.975) 258(4.25,20.975) 259(3.75,20.975) 260(3.25,20.975) 261(2.75,20.975) 262(2.25,20.975) 263(1.75,20.975) 264(1.25,20.975) 265(0.75,20.975) 266(0.25,20.975) 267(-0.25,20.975) 268(-0.75,20.975) 269(-1.25,20.975) 270(-1.75,20.975) 271(-2.25,20.975) 272(-2.75,20.975) 273(-3.25,20.975) 274(-3.75,20.975) 275(-4.25,20.975) 276(-4.75,20.975) 277(-5.25,20.975) 278(-5.75,20.975) 279(-6.25,20.975) 280(-6.75,20.975) 281(-7.25,20.975) 282(-7.75,20.975) 283(-8.25,20.975) 284(-8.75,20.975) 285(-9.25,20.975) 286(-9.75,20.975) 287(-10.25,20.975) 288(-10.75,20.975) 289(-11.25,20.975) 290(-11.75,20.975) 291(-12.25,20.975) 292(-12.75,20.975) 293(-13.25,20.975) 294(-13.75,20.975) 295(-14.25,20.975) 296(-14.75,20.975) 297(-15.25,20.975) 298(-15.75,20.975) 299(-16.25,20.975) 300(-16.75,20.975) 301(-17.25,20.975) 302(-17.75,20.975) 303(-18.25,20.975) 304(-18.75,20.975)
Top Overlay:
  circle w0.25: c-20.975,19.45 r0.125
  lines w0.2: -19.875,-19.875 -19.875,19.875 19.875,19.875 19.875,-19.875 -19.875,-19.875

## F-QFP40x40-G304/Y1.8N [mm]
pads (304):
  rect 1.8x0.3 smd: 1(-20.83,18.75) 2(-20.83,18.25) 3(-20.83,17.75) 4(-20.83,17.25) 5(-20.83,16.75) 6(-20.83,16.25) 7(-20.83,15.75) 8(-20.83,15.25) 9(-20.83,14.75) 10(-20.83,14.25) 11(-20.83,13.75) 12(-20.83,13.25) 13(-20.83,12.75) 14(-20.83,12.25) 15(-20.83,11.75) 16(-20.83,11.25) 17(-20.83,10.75) 18(-20.83,10.25) 19(-20.83,9.75) 20(-20.83,9.25) 21(-20.83,8.75) 22(-20.83,8.25) 23(-20.83,7.75) 24(-20.83,7.25) 25(-20.83,6.75) 26(-20.83,6.25) 27(-20.83,5.75) 28(-20.83,5.25) 29(-20.83,4.75) 30(-20.83,4.25) 31(-20.83,3.75) 32(-20.83,3.25) 33(-20.83,2.75) 34(-20.83,2.25) 35(-20.83,1.75) 36(-20.83,1.25) 37(-20.83,0.75) 38(-20.83,0.25) 39(-20.83,-0.25) 40(-20.83,-0.75) 41(-20.83,-1.25) 42(-20.83,-1.75) 43(-20.83,-2.25) 44(-20.83,-2.75) 45(-20.83,-3.25) 46(-20.83,-3.75) 47(-20.83,-4.25) 48(-20.83,-4.75) 49(-20.83,-5.25) 50(-20.83,-5.75) 51(-20.83,-6.25) 52(-20.83,-6.75) 53(-20.83,-7.25) 54(-20.83,-7.75) 55(-20.83,-8.25) 56(-20.83,-8.75) 57(-20.83,-9.25) 58(-20.83,-9.75) 59(-20.83,-10.25) 60(-20.83,-10.75) 61(-20.83,-11.25) 62(-20.83,-11.75) 63(-20.83,-12.25) 64(-20.83,-12.75) 65(-20.83,-13.25) 66(-20.83,-13.75) 67(-20.83,-14.25) 68(-20.83,-14.75) 69(-20.83,-15.25) 70(-20.83,-15.75) 71(-20.83,-16.25) 72(-20.83,-16.75) 73(-20.83,-17.25) 74(-20.83,-17.75) 75(-20.83,-18.25) 76(-20.83,-18.75) 153(20.83,-18.75) 154(20.83,-18.25) 155(20.83,-17.75) 156(20.83,-17.25) 157(20.83,-16.75) 158(20.83,-16.25) 159(20.83,-15.75) 160(20.83,-15.25) 161(20.83,-14.75) 162(20.83,-14.25) 163(20.83,-13.75) 164(20.83,-13.25) 165(20.83,-12.75) 166(20.83,-12.25) 167(20.83,-11.75) 168(20.83,-11.25) 169(20.83,-10.75) 170(20.83,-10.25) 171(20.83,-9.75) 172(20.83,-9.25) 173(20.83,-8.75) 174(20.83,-8.25) 175(20.83,-7.75) 176(20.83,-7.25) 177(20.83,-6.75) 178(20.83,-6.25) 179(20.83,-5.75) 180(20.83,-5.25) 181(20.83,-4.75) 182(20.83,-4.25) 183(20.83,-3.75) 184(20.83,-3.25) 185(20.83,-2.75) 186(20.83,-2.25) 187(20.83,-1.75) 188(20.83,-1.25) 189(20.83,-0.75) 190(20.83,-0.25) 191(20.83,0.25) 192(20.83,0.75) 193(20.83,1.25) 194(20.83,1.75) 195(20.83,2.25) 196(20.83,2.75) 197(20.83,3.25) 198(20.83,3.75) 199(20.83,4.25) 200(20.83,4.75) 201(20.83,5.25) 202(20.83,5.75) 203(20.83,6.25) 204(20.83,6.75) 205(20.83,7.25) 206(20.83,7.75) 207(20.83,8.25) 208(20.83,8.75) 209(20.83,9.25) 210(20.83,9.75) 211(20.83,10.25) 212(20.83,10.75) 213(20.83,11.25) 214(20.83,11.75) 215(20.83,12.25) 216(20.83,12.75) 217(20.83,13.25) 218(20.83,13.75) 219(20.83,14.25) 220(20.83,14.75) 221(20.83,15.25) 222(20.83,15.75) 223(20.83,16.25) 224(20.83,16.75) 225(20.83,17.25) 226(20.83,17.75) 227(20.83,18.25) 228(20.83,18.75)
  rect 0.3x1.8 smd: 77(-18.75,-20.83) 78(-18.25,-20.83) 79(-17.75,-20.83) 80(-17.25,-20.83) 81(-16.75,-20.83) 82(-16.25,-20.83) 83(-15.75,-20.83) 84(-15.25,-20.83) 85(-14.75,-20.83) 86(-14.25,-20.83) 87(-13.75,-20.83) 88(-13.25,-20.83) 89(-12.75,-20.83) 90(-12.25,-20.83) 91(-11.75,-20.83) 92(-11.25,-20.83) 93(-10.75,-20.83) 94(-10.25,-20.83) 95(-9.75,-20.83) 96(-9.25,-20.83) 97(-8.75,-20.83) 98(-8.25,-20.83) 99(-7.75,-20.83) 100(-7.25,-20.83) 101(-6.75,-20.83) 102(-6.25,-20.83) 103(-5.75,-20.83) 104(-5.25,-20.83) 105(-4.75,-20.83) 106(-4.25,-20.83) 107(-3.75,-20.83) 108(-3.25,-20.83) 109(-2.75,-20.83) 110(-2.25,-20.83) 111(-1.75,-20.83) 112(-1.25,-20.83) 113(-0.75,-20.83) 114(-0.25,-20.83) 115(0.25,-20.83) 116(0.75,-20.83) 117(1.25,-20.83) 118(1.75,-20.83) 119(2.25,-20.83) 120(2.75,-20.83) 121(3.25,-20.83) 122(3.75,-20.83) 123(4.25,-20.83) 124(4.75,-20.83) 125(5.25,-20.83) 126(5.75,-20.83) 127(6.25,-20.83) 128(6.75,-20.83) 129(7.25,-20.83) 130(7.75,-20.83) 131(8.25,-20.83) 132(8.75,-20.83) 133(9.25,-20.83) 134(9.75,-20.83) 135(10.25,-20.83) 136(10.75,-20.83) 137(11.25,-20.83) 138(11.75,-20.83) 139(12.25,-20.83) 140(12.75,-20.83) 141(13.25,-20.83) 142(13.75,-20.83) 143(14.25,-20.83) 144(14.75,-20.83) 145(15.25,-20.83) 146(15.75,-20.83) 147(16.25,-20.83) 148(16.75,-20.83) 149(17.25,-20.83) 150(17.75,-20.83) 151(18.25,-20.83) 152(18.75,-20.83) 229(18.75,20.83) 230(18.25,20.83) 231(17.75,20.83) 232(17.25,20.83) 233(16.75,20.83) 234(16.25,20.83) 235(15.75,20.83) 236(15.25,20.83) 237(14.75,20.83) 238(14.25,20.83) 239(13.75,20.83) 240(13.25,20.83) 241(12.75,20.83) 242(12.25,20.83) 243(11.75,20.83) 244(11.25,20.83) 245(10.75,20.83) 246(10.25,20.83) 247(9.75,20.83) 248(9.25,20.83) 249(8.75,20.83) 250(8.25,20.83) 251(7.75,20.83) 252(7.25,20.83) 253(6.75,20.83) 254(6.25,20.83) 255(5.75,20.83) 256(5.25,20.83) 257(4.75,20.83) 258(4.25,20.83) 259(3.75,20.83) 260(3.25,20.83) 261(2.75,20.83) 262(2.25,20.83) 263(1.75,20.83) 264(1.25,20.83) 265(0.75,20.83) 266(0.25,20.83) 267(-0.25,20.83) 268(-0.75,20.83) 269(-1.25,20.83) 270(-1.75,20.83) 271(-2.25,20.83) 272(-2.75,20.83) 273(-3.25,20.83) 274(-3.75,20.83) 275(-4.25,20.83) 276(-4.75,20.83) 277(-5.25,20.83) 278(-5.75,20.83) 279(-6.25,20.83) 280(-6.75,20.83) 281(-7.25,20.83) 282(-7.75,20.83) 283(-8.25,20.83) 284(-8.75,20.83) 285(-9.25,20.83) 286(-9.75,20.83) 287(-10.25,20.83) 288(-10.75,20.83) 289(-11.25,20.83) 290(-11.75,20.83) 291(-12.25,20.83) 292(-12.75,20.83) 293(-13.25,20.83) 294(-13.75,20.83) 295(-14.25,20.83) 296(-14.75,20.83) 297(-15.25,20.83) 298(-15.75,20.83) 299(-16.25,20.83) 300(-16.75,20.83) 301(-17.25,20.83) 302(-17.75,20.83) 303(-18.25,20.83) 304(-18.75,20.83)
Top Overlay:
  circle w0.25: c-20.83,19.45 r0.125
  lines w0.2: -19.525,-19.525 -19.525,19.525 19.525,19.525 19.525,-19.525 -19.525,-19.525

## F-QFP40X40-G312/N [mm]
pads (312):
  rect 1.6x0.3 smd: 1(-20.6,19.25) 2(-20.6,18.75) 3(-20.6,18.25) 4(-20.6,17.75) 5(-20.6,17.25) 6(-20.6,16.75) 7(-20.6,16.25) 8(-20.6,15.75) 9(-20.6,15.25) 10(-20.6,14.75) 11(-20.6,14.25) 12(-20.6,13.75) 13(-20.6,13.25) 14(-20.6,12.75) 15(-20.6,12.25) 16(-20.6,11.75) 17(-20.6,11.25) 18(-20.6,10.75) 19(-20.6,10.25) 20(-20.6,9.75) 21(-20.6,9.25) 22(-20.6,8.75) 23(-20.6,8.25) 24(-20.6,7.75) 25(-20.6,7.25) 26(-20.6,6.75) 27(-20.6,6.25) 28(-20.6,5.75) 29(-20.6,5.25) 30(-20.6,4.75) 31(-20.6,4.25) 32(-20.6,3.75) 33(-20.6,3.25) 34(-20.6,2.75) 35(-20.6,2.25) 36(-20.6,1.75) 37(-20.6,1.25) 38(-20.6,0.75) 39(-20.6,0.25) 40(-20.6,-0.25) 41(-20.6,-0.75) 42(-20.6,-1.25) 43(-20.6,-1.75) 44(-20.6,-2.25) 45(-20.6,-2.75) 46(-20.6,-3.25) 47(-20.6,-3.75) 48(-20.6,-4.25) 49(-20.6,-4.75) 50(-20.6,-5.25) 51(-20.6,-5.75) 52(-20.6,-6.25) 53(-20.6,-6.75) 54(-20.6,-7.25) 55(-20.6,-7.75) 56(-20.6,-8.25) 57(-20.6,-8.75) 58(-20.6,-9.25) 59(-20.6,-9.75) 60(-20.6,-10.25) 61(-20.6,-10.75) 62(-20.6,-11.25) 63(-20.6,-11.75) 64(-20.6,-12.25) 65(-20.6,-12.75) 66(-20.6,-13.25) 67(-20.6,-13.75) 68(-20.6,-14.25) 69(-20.6,-14.75) 70(-20.6,-15.25) 71(-20.6,-15.75) 72(-20.6,-16.25) 73(-20.6,-16.75) 74(-20.6,-17.25) 75(-20.6,-17.75) 76(-20.6,-18.25) 77(-20.6,-18.75) 78(-20.6,-19.25) 157(20.6,-19.25) 158(20.6,-18.75) 159(20.6,-18.25) 160(20.6,-17.75) 161(20.6,-17.25) 162(20.6,-16.75) 163(20.6,-16.25) 164(20.6,-15.75) 165(20.6,-15.25) 166(20.6,-14.75) 167(20.6,-14.25) 168(20.6,-13.75) 169(20.6,-13.25) 170(20.6,-12.75) 171(20.6,-12.25) 172(20.6,-11.75) 173(20.6,-11.25) 174(20.6,-10.75) 175(20.6,-10.25) 176(20.6,-9.75) 177(20.6,-9.25) 178(20.6,-8.75) 179(20.6,-8.25) 180(20.6,-7.75) 181(20.6,-7.25) 182(20.6,-6.75) 183(20.6,-6.25) 184(20.6,-5.75) 185(20.6,-5.25) 186(20.6,-4.75) 187(20.6,-4.25) 188(20.6,-3.75) 189(20.6,-3.25) 190(20.6,-2.75) 191(20.6,-2.25) 192(20.6,-1.75) 193(20.6,-1.25) 194(20.6,-0.75) 195(20.6,-0.25) 196(20.6,0.25) 197(20.6,0.75) 198(20.6,1.25) 199(20.6,1.75) 200(20.6,2.25) 201(20.6,2.75) 202(20.6,3.25) 203(20.6,3.75) 204(20.6,4.25) 205(20.6,4.75) 206(20.6,5.25) 207(20.6,5.75) 208(20.6,6.25) 209(20.6,6.75) 210(20.6,7.25) 211(20.6,7.75) 212(20.6,8.25) 213(20.6,8.75) 214(20.6,9.25) 215(20.6,9.75) 216(20.6,10.25) 217(20.6,10.75) 218(20.6,11.25) 219(20.6,11.75) 220(20.6,12.25) 221(20.6,12.75) 222(20.6,13.25) 223(20.6,13.75) 224(20.6,14.25) 225(20.6,14.75) 226(20.6,15.25) 227(20.6,15.75) 228(20.6,16.25) 229(20.6,16.75) 230(20.6,17.25) 231(20.6,17.75) 232(20.6,18.25) 233(20.6,18.75) 234(20.6,19.25)
  rect 0.3x1.6 smd: 79(-19.25,-20.6) 80(-18.75,-20.6) 81(-18.25,-20.6) 82(-17.75,-20.6) 83(-17.25,-20.6) 84(-16.75,-20.6) 85(-16.25,-20.6) 86(-15.75,-20.6) 87(-15.25,-20.6) 88(-14.75,-20.6) 89(-14.25,-20.6) 90(-13.75,-20.6) 91(-13.25,-20.6) 92(-12.75,-20.6) 93(-12.25,-20.6) 94(-11.75,-20.6) 95(-11.25,-20.6) 96(-10.75,-20.6) 97(-10.25,-20.6) 98(-9.75,-20.6) 99(-9.25,-20.6) 100(-8.75,-20.6) 101(-8.25,-20.6) 102(-7.75,-20.6) 103(-7.25,-20.6) 104(-6.75,-20.6) 105(-6.25,-20.6) 106(-5.75,-20.6) 107(-5.25,-20.6) 108(-4.75,-20.6) 109(-4.25,-20.6) 110(-3.75,-20.6) 111(-3.25,-20.6) 112(-2.75,-20.6) 113(-2.25,-20.6) 114(-1.75,-20.6) 115(-1.25,-20.6) 116(-0.75,-20.6) 117(-0.25,-20.6) 118(0.25,-20.6) 119(0.75,-20.6) 120(1.25,-20.6) 121(1.75,-20.6) 122(2.25,-20.6) 123(2.75,-20.6) 124(3.25,-20.6) 125(3.75,-20.6) 126(4.25,-20.6) 127(4.75,-20.6) 128(5.25,-20.6) 129(5.75,-20.6) 130(6.25,-20.6) 131(6.75,-20.6) 132(7.25,-20.6) 133(7.75,-20.6) 134(8.25,-20.6) 135(8.75,-20.6) 136(9.25,-20.6) 137(9.75,-20.6) 138(10.25,-20.6) 139(10.75,-20.6) 140(11.25,-20.6) 141(11.75,-20.6) 142(12.25,-20.6) 143(12.75,-20.6) 144(13.25,-20.6) 145(13.75,-20.6) 146(14.25,-20.6) 147(14.75,-20.6) 148(15.25,-20.6) 149(15.75,-20.6) 150(16.25,-20.6) 151(16.75,-20.6) 152(17.25,-20.6) 153(17.75,-20.6) 154(18.25,-20.6) 155(18.75,-20.6) 156(19.25,-20.6) 235(19.25,20.6) 236(18.75,20.6) 237(18.25,20.6) 238(17.75,20.6) 239(17.25,20.6) 240(16.75,20.6) 241(16.25,20.6) 242(15.75,20.6) 243(15.25,20.6) 244(14.75,20.6) 245(14.25,20.6) 246(13.75,20.6) 247(13.25,20.6) 248(12.75,20.6) 249(12.25,20.6) 250(11.75,20.6) 251(11.25,20.6) 252(10.75,20.6) 253(10.25,20.6) 254(9.75,20.6) 255(9.25,20.6) 256(8.75,20.6) 257(8.25,20.6) 258(7.75,20.6) 259(7.25,20.6) 260(6.75,20.6) 261(6.25,20.6) 262(5.75,20.6) 263(5.25,20.6) 264(4.75,20.6) 265(4.25,20.6) 266(3.75,20.6) 267(3.25,20.6) 268(2.75,20.6) 269(2.25,20.6) 270(1.75,20.6) 271(1.25,20.6) 272(0.75,20.6) 273(0.25,20.6) 274(-0.25,20.6) 275(-0.75,20.6) 276(-1.25,20.6) 277(-1.75,20.6) 278(-2.25,20.6) 279(-2.75,20.6) 280(-3.25,20.6) 281(-3.75,20.6) 282(-4.25,20.6) 283(-4.75,20.6) 284(-5.25,20.6) 285(-5.75,20.6) 286(-6.25,20.6) 287(-6.75,20.6) 288(-7.25,20.6) 289(-7.75,20.6) 290(-8.25,20.6) 291(-8.75,20.6) 292(-9.25,20.6) 293(-9.75,20.6) 294(-10.25,20.6) 295(-10.75,20.6) 296(-11.25,20.6) 297(-11.75,20.6) 298(-12.25,20.6) 299(-12.75,20.6) 300(-13.25,20.6) 301(-13.75,20.6) 302(-14.25,20.6) 303(-14.75,20.6) 304(-15.25,20.6) 305(-15.75,20.6) 306(-16.25,20.6) 307(-16.75,20.6) 308(-17.25,20.6) 309(-17.75,20.6) 310(-18.25,20.6) 311(-18.75,20.6) 312(-19.25,20.6)
Top Overlay:
  circle w0.25: c-21.96,19.25 r0.125
  lines w0.2: -19.4,-19.4 -19.4,19.4 19.4,19.4 19.4,-19.4 -19.4,-19.4

## F-QFP44X44-G336/N [mm]
pads (336):
  rect 1.6x0.3 smd: 1(-22.6,20.75) 2(-22.6,20.25) 3(-22.6,19.75) 4(-22.6,19.25) 5(-22.6,18.75) 6(-22.6,18.25) 7(-22.6,17.75) 8(-22.6,17.25) 9(-22.6,16.75) 10(-22.6,16.25) 11(-22.6,15.75) 12(-22.6,15.25) 13(-22.6,14.75) 14(-22.6,14.25) 15(-22.6,13.75) 16(-22.6,13.25) 17(-22.6,12.75) 18(-22.6,12.25) 19(-22.6,11.75) 20(-22.6,11.25) 21(-22.6,10.75) 22(-22.6,10.25) 23(-22.6,9.75) 24(-22.6,9.25) 25(-22.6,8.75) 26(-22.6,8.25) 27(-22.6,7.75) 28(-22.6,7.25) 29(-22.6,6.75) 30(-22.6,6.25) 31(-22.6,5.75) 32(-22.6,5.25) 33(-22.6,4.75) 34(-22.6,4.25) 35(-22.6,3.75) 36(-22.6,3.25) 37(-22.6,2.75) 38(-22.6,2.25) 39(-22.6,1.75) 40(-22.6,1.25) 41(-22.6,0.75) 42(-22.6,0.25) 43(-22.6,-0.25) 44(-22.6,-0.75) 45(-22.6,-1.25) 46(-22.6,-1.75) 47(-22.6,-2.25) 48(-22.6,-2.75) 49(-22.6,-3.25) 50(-22.6,-3.75) 51(-22.6,-4.25) 52(-22.6,-4.75) 53(-22.6,-5.25) 54(-22.6,-5.75) 55(-22.6,-6.25) 56(-22.6,-6.75) 57(-22.6,-7.25) 58(-22.6,-7.75) 59(-22.6,-8.25) 60(-22.6,-8.75) 61(-22.6,-9.25) 62(-22.6,-9.75) 63(-22.6,-10.25) 64(-22.6,-10.75) 65(-22.6,-11.25) 66(-22.6,-11.75) 67(-22.6,-12.25) 68(-22.6,-12.75) 69(-22.6,-13.25) 70(-22.6,-13.75) 71(-22.6,-14.25) 72(-22.6,-14.75) 73(-22.6,-15.25) 74(-22.6,-15.75) 75(-22.6,-16.25) 76(-22.6,-16.75) 77(-22.6,-17.25) 78(-22.6,-17.75) 79(-22.6,-18.25) 80(-22.6,-18.75) 81(-22.6,-19.25) 82(-22.6,-19.75) 83(-22.6,-20.25) 84(-22.6,-20.75) 169(22.6,-20.75) 170(22.6,-20.25) 171(22.6,-19.75) 172(22.6,-19.25) 173(22.6,-18.75) 174(22.6,-18.25) 175(22.6,-17.75) 176(22.6,-17.25) 177(22.6,-16.75) 178(22.6,-16.25) 179(22.6,-15.75) 180(22.6,-15.25) 181(22.6,-14.75) 182(22.6,-14.25) 183(22.6,-13.75) 184(22.6,-13.25) 185(22.6,-12.75) 186(22.6,-12.25) 187(22.6,-11.75) 188(22.6,-11.25) 189(22.6,-10.75) 190(22.6,-10.25) 191(22.6,-9.75) 192(22.6,-9.25) 193(22.6,-8.75) 194(22.6,-8.25) 195(22.6,-7.75) 196(22.6,-7.25) 197(22.6,-6.75) 198(22.6,-6.25) 199(22.6,-5.75) 200(22.6,-5.25) 201(22.6,-4.75) 202(22.6,-4.25) 203(22.6,-3.75) 204(22.6,-3.25) 205(22.6,-2.75) 206(22.6,-2.25) 207(22.6,-1.75) 208(22.6,-1.25) 209(22.6,-0.75) 210(22.6,-0.25) 211(22.6,0.25) 212(22.6,0.75) 213(22.6,1.25) 214(22.6,1.75) 215(22.6,2.25) 216(22.6,2.75) 217(22.6,3.25) 218(22.6,3.75) 219(22.6,4.25) 220(22.6,4.75) 221(22.6,5.25) 222(22.6,5.75) 223(22.6,6.25) 224(22.6,6.75) 225(22.6,7.25) 226(22.6,7.75) 227(22.6,8.25) 228(22.6,8.75) 229(22.6,9.25) 230(22.6,9.75) 231(22.6,10.25) 232(22.6,10.75) 233(22.6,11.25) 234(22.6,11.75) 235(22.6,12.25) 236(22.6,12.75) 237(22.6,13.25) 238(22.6,13.75) 239(22.6,14.25) 240(22.6,14.75) 241(22.6,15.25) 242(22.6,15.75) 243(22.6,16.25) 244(22.6,16.75) 245(22.6,17.25) 246(22.6,17.75) 247(22.6,18.25) 248(22.6,18.75) 249(22.6,19.25) 250(22.6,19.75) 251(22.6,20.25) 252(22.6,20.75)
  rect 0.3x1.6 smd: 85(-20.75,-22.6) 86(-20.25,-22.6) 87(-19.75,-22.6) 88(-19.25,-22.6) 89(-18.75,-22.6) 90(-18.25,-22.6) 91(-17.75,-22.6) 92(-17.25,-22.6) 93(-16.75,-22.6) 94(-16.25,-22.6) 95(-15.75,-22.6) 96(-15.25,-22.6) 97(-14.75,-22.6) 98(-14.25,-22.6) 99(-13.75,-22.6) 100(-13.25,-22.6) 101(-12.75,-22.6) 102(-12.25,-22.6) 103(-11.75,-22.6) 104(-11.25,-22.6) 105(-10.75,-22.6) 106(-10.25,-22.6) 107(-9.75,-22.6) 108(-9.25,-22.6) 109(-8.75,-22.6) 110(-8.25,-22.6) 111(-7.75,-22.6) 112(-7.25,-22.6) 113(-6.75,-22.6) 114(-6.25,-22.6) 115(-5.75,-22.6) 116(-5.25,-22.6) 117(-4.75,-22.6) 118(-4.25,-22.6) 119(-3.75,-22.6) 120(-3.25,-22.6) 121(-2.75,-22.6) 122(-2.25,-22.6) 123(-1.75,-22.6) 124(-1.25,-22.6) 125(-0.75,-22.6) 126(-0.25,-22.6) 127(0.25,-22.6) 128(0.75,-22.6) 129(1.25,-22.6) 130(1.75,-22.6) 131(2.25,-22.6) 132(2.75,-22.6) 133(3.25,-22.6) 134(3.75,-22.6) 135(4.25,-22.6) 136(4.75,-22.6) 137(5.25,-22.6) 138(5.75,-22.6) 139(6.25,-22.6) 140(6.75,-22.6) 141(7.25,-22.6) 142(7.75,-22.6) 143(8.25,-22.6) 144(8.75,-22.6) 145(9.25,-22.6) 146(9.75,-22.6) 147(10.25,-22.6) 148(10.75,-22.6) 149(11.25,-22.6) 150(11.75,-22.6) 151(12.25,-22.6) 152(12.75,-22.6) 153(13.25,-22.6) 154(13.75,-22.6) 155(14.25,-22.6) 156(14.75,-22.6) 157(15.25,-22.6) 158(15.75,-22.6) 159(16.25,-22.6) 160(16.75,-22.6) 161(17.25,-22.6) 162(17.75,-22.6) 163(18.25,-22.6) 164(18.75,-22.6) 165(19.25,-22.6) 166(19.75,-22.6) 167(20.25,-22.6) 168(20.75,-22.6) 253(20.75,22.6) 254(20.25,22.6) 255(19.75,22.6) 256(19.25,22.6) 257(18.75,22.6) 258(18.25,22.6) 259(17.75,22.6) 260(17.25,22.6) 261(16.75,22.6) 262(16.25,22.6) 263(15.75,22.6) 264(15.25,22.6) 265(14.75,22.6) 266(14.25,22.6) 267(13.75,22.6) 268(13.25,22.6) 269(12.75,22.6) 270(12.25,22.6) 271(11.75,22.6) 272(11.25,22.6) 273(10.75,22.6) 274(10.25,22.6) 275(9.75,22.6) 276(9.25,22.6) 277(8.75,22.6) 278(8.25,22.6) 279(7.75,22.6) 280(7.25,22.6) 281(6.75,22.6) 282(6.25,22.6) 283(5.75,22.6) 284(5.25,22.6) 285(4.75,22.6) 286(4.25,22.6) 287(3.75,22.6) 288(3.25,22.6) 289(2.75,22.6) 290(2.25,22.6) 291(1.75,22.6) 292(1.25,22.6) 293(0.75,22.6) 294(0.25,22.6) 295(-0.25,22.6) 296(-0.75,22.6) 297(-1.25,22.6) 298(-1.75,22.6) 299(-2.25,22.6) 300(-2.75,22.6) 301(-3.25,22.6) 302(-3.75,22.6) 303(-4.25,22.6) 304(-4.75,22.6) 305(-5.25,22.6) 306(-5.75,22.6) 307(-6.25,22.6) 308(-6.75,22.6) 309(-7.25,22.6) 310(-7.75,22.6) 311(-8.25,22.6) 312(-8.75,22.6) 313(-9.25,22.6) 314(-9.75,22.6) 315(-10.25,22.6) 316(-10.75,22.6) 317(-11.25,22.6) 318(-11.75,22.6) 319(-12.25,22.6) 320(-12.75,22.6) 321(-13.25,22.6) 322(-13.75,22.6) 323(-14.25,22.6) 324(-14.75,22.6) 325(-15.25,22.6) 326(-15.75,22.6) 327(-16.25,22.6) 328(-16.75,22.6) 329(-17.25,22.6) 330(-17.75,22.6) 331(-18.25,22.6) 332(-18.75,22.6) 333(-19.25,22.6) 334(-19.75,22.6) 335(-20.25,22.6) 336(-20.75,22.6)
Top Overlay:
  circle w0.25: c-23.96,20.75 r0.125
  lines w0.2: -21.4,-21.4 21.4,-21.4 21.4,21.4 -21.4,21.4 -21.4,-21.4

## F-QFP44X44-G344/N [mm]
pads (344):
  rect 1.6x0.3 smd: 1(-22.6,21.25) 2(-22.6,20.75) 3(-22.6,20.25) 4(-22.6,19.75) 5(-22.6,19.25) 6(-22.6,18.75) 7(-22.6,18.25) 8(-22.6,17.75) 9(-22.6,17.25) 10(-22.6,16.75) 11(-22.6,16.25) 12(-22.6,15.75) 13(-22.6,15.25) 14(-22.6,14.75) 15(-22.6,14.25) 16(-22.6,13.75) 17(-22.6,13.25) 18(-22.6,12.75) 19(-22.6,12.25) 20(-22.6,11.75) 21(-22.6,11.25) 22(-22.6,10.75) 23(-22.6,10.25) 24(-22.6,9.75) 25(-22.6,9.25) 26(-22.6,8.75) 27(-22.6,8.25) 28(-22.6,7.75) 29(-22.6,7.25) 30(-22.6,6.75) 31(-22.6,6.25) 32(-22.6,5.75) 33(-22.6,5.25) 34(-22.6,4.75) 35(-22.6,4.25) 36(-22.6,3.75) 37(-22.6,3.25) 38(-22.6,2.75) 39(-22.6,2.25) 40(-22.6,1.75) 41(-22.6,1.25) 42(-22.6,0.75) 43(-22.6,0.25) 44(-22.6,-0.25) 45(-22.6,-0.75) 46(-22.6,-1.25) 47(-22.6,-1.75) 48(-22.6,-2.25) 49(-22.6,-2.75) 50(-22.6,-3.25) 51(-22.6,-3.75) 52(-22.6,-4.25) 53(-22.6,-4.75) 54(-22.6,-5.25) 55(-22.6,-5.75) 56(-22.6,-6.25) 57(-22.6,-6.75) 58(-22.6,-7.25) 59(-22.6,-7.75) 60(-22.6,-8.25) 61(-22.6,-8.75) 62(-22.6,-9.25) 63(-22.6,-9.75) 64(-22.6,-10.25) 65(-22.6,-10.75) 66(-22.6,-11.25) 67(-22.6,-11.75) 68(-22.6,-12.25) 69(-22.6,-12.75) 70(-22.6,-13.25) 71(-22.6,-13.75) 72(-22.6,-14.25) 73(-22.6,-14.75) 74(-22.6,-15.25) 75(-22.6,-15.75) 76(-22.6,-16.25) 77(-22.6,-16.75) 78(-22.6,-17.25) 79(-22.6,-17.75) 80(-22.6,-18.25) 81(-22.6,-18.75) 82(-22.6,-19.25) 83(-22.6,-19.75) 84(-22.6,-20.25) 85(-22.6,-20.75) 86(-22.6,-21.25) 173(22.6,-21.25) 174(22.6,-20.75) 175(22.6,-20.25) 176(22.6,-19.75) 177(22.6,-19.25) 178(22.6,-18.75) 179(22.6,-18.25) 180(22.6,-17.75) 181(22.6,-17.25) 182(22.6,-16.75) 183(22.6,-16.25) 184(22.6,-15.75) 185(22.6,-15.25) 186(22.6,-14.75) 187(22.6,-14.25) 188(22.6,-13.75) 189(22.6,-13.25) 190(22.6,-12.75) 191(22.6,-12.25) 192(22.6,-11.75) 193(22.6,-11.25) 194(22.6,-10.75) 195(22.6,-10.25) 196(22.6,-9.75) 197(22.6,-9.25) 198(22.6,-8.75) 199(22.6,-8.25) 200(22.6,-7.75) 201(22.6,-7.25) 202(22.6,-6.75) 203(22.6,-6.25) 204(22.6,-5.75) 205(22.6,-5.25) 206(22.6,-4.75) 207(22.6,-4.25) 208(22.6,-3.75) 209(22.6,-3.25) 210(22.6,-2.75) 211(22.6,-2.25) 212(22.6,-1.75) 213(22.6,-1.25) 214(22.6,-0.75) 215(22.6,-0.25) 216(22.6,0.25) 217(22.6,0.75) 218(22.6,1.25) 219(22.6,1.75) 220(22.6,2.25) 221(22.6,2.75) 222(22.6,3.25) 223(22.6,3.75) 224(22.6,4.25) 225(22.6,4.75) 226(22.6,5.25) 227(22.6,5.75) 228(22.6,6.25) 229(22.6,6.75) 230(22.6,7.25) 231(22.6,7.75) 232(22.6,8.25) 233(22.6,8.75) 234(22.6,9.25) 235(22.6,9.75) 236(22.6,10.25) 237(22.6,10.75) 238(22.6,11.25) 239(22.6,11.75) 240(22.6,12.25) 241(22.6,12.75) 242(22.6,13.25) 243(22.6,13.75) 244(22.6,14.25) 245(22.6,14.75) 246(22.6,15.25) 247(22.6,15.75) 248(22.6,16.25) 249(22.6,16.75) 250(22.6,17.25) 251(22.6,17.75) 252(22.6,18.25) 253(22.6,18.75) 254(22.6,19.25) 255(22.6,19.75) 256(22.6,20.25) 257(22.6,20.75) 258(22.6,21.25)
  rect 0.3x1.6 smd: 87(-21.25,-22.6) 88(-20.75,-22.6) 89(-20.25,-22.6) 90(-19.75,-22.6) 91(-19.25,-22.6) 92(-18.75,-22.6) 93(-18.25,-22.6) 94(-17.75,-22.6) 95(-17.25,-22.6) 96(-16.75,-22.6) 97(-16.25,-22.6) 98(-15.75,-22.6) 99(-15.25,-22.6) 100(-14.75,-22.6) 101(-14.25,-22.6) 102(-13.75,-22.6) 103(-13.25,-22.6) 104(-12.75,-22.6) 105(-12.25,-22.6) 106(-11.75,-22.6) 107(-11.25,-22.6) 108(-10.75,-22.6) 109(-10.25,-22.6) 110(-9.75,-22.6) 111(-9.25,-22.6) 112(-8.75,-22.6) 113(-8.25,-22.6) 114(-7.75,-22.6) 115(-7.25,-22.6) 116(-6.75,-22.6) 117(-6.25,-22.6) 118(-5.75,-22.6) 119(-5.25,-22.6) 120(-4.75,-22.6) 121(-4.25,-22.6) 122(-3.75,-22.6) 123(-3.25,-22.6) 124(-2.75,-22.6) 125(-2.25,-22.6) 126(-1.75,-22.6) 127(-1.25,-22.6) 128(-0.75,-22.6) 129(-0.25,-22.6) 130(0.25,-22.6) 131(0.75,-22.6) 132(1.25,-22.6) 133(1.75,-22.6) 134(2.25,-22.6) 135(2.75,-22.6) 136(3.25,-22.6) 137(3.75,-22.6) 138(4.25,-22.6) 139(4.75,-22.6) 140(5.25,-22.6) 141(5.75,-22.6) 142(6.25,-22.6) 143(6.75,-22.6) 144(7.25,-22.6) 145(7.75,-22.6) 146(8.25,-22.6) 147(8.75,-22.6) 148(9.25,-22.6) 149(9.75,-22.6) 150(10.25,-22.6) 151(10.75,-22.6) 152(11.25,-22.6) 153(11.75,-22.6) 154(12.25,-22.6) 155(12.75,-22.6) 156(13.25,-22.6) 157(13.75,-22.6) 158(14.25,-22.6) 159(14.75,-22.6) 160(15.25,-22.6) 161(15.75,-22.6) 162(16.25,-22.6) 163(16.75,-22.6) 164(17.25,-22.6) 165(17.75,-22.6) 166(18.25,-22.6) 167(18.75,-22.6) 168(19.25,-22.6) 169(19.75,-22.6) 170(20.25,-22.6) 171(20.75,-22.6) 172(21.25,-22.6) 259(21.25,22.6) 260(20.75,22.6) 261(20.25,22.6) 262(19.75,22.6) 263(19.25,22.6) 264(18.75,22.6) 265(18.25,22.6) 266(17.75,22.6) 267(17.25,22.6) 268(16.75,22.6) 269(16.25,22.6) 270(15.75,22.6) 271(15.25,22.6) 272(14.75,22.6) 273(14.25,22.6) 274(13.75,22.6) 275(13.25,22.6) 276(12.75,22.6) 277(12.25,22.6) 278(11.75,22.6) 279(11.25,22.6) 280(10.75,22.6) 281(10.25,22.6) 282(9.75,22.6) 283(9.25,22.6) 284(8.75,22.6) 285(8.25,22.6) 286(7.75,22.6) 287(7.25,22.6) 288(6.75,22.6) 289(6.25,22.6) 290(5.75,22.6) 291(5.25,22.6) 292(4.75,22.6) 293(4.25,22.6) 294(3.75,22.6) 295(3.25,22.6) 296(2.75,22.6) 297(2.25,22.6) 298(1.75,22.6) 299(1.25,22.6) 300(0.75,22.6) 301(0.25,22.6) 302(-0.25,22.6) 303(-0.75,22.6) 304(-1.25,22.6) 305(-1.75,22.6) 306(-2.25,22.6) 307(-2.75,22.6) 308(-3.25,22.6) 309(-3.75,22.6) 310(-4.25,22.6) 311(-4.75,22.6) 312(-5.25,22.6) 313(-5.75,22.6) 314(-6.25,22.6) 315(-6.75,22.6) 316(-7.25,22.6) 317(-7.75,22.6) 318(-8.25,22.6) 319(-8.75,22.6) 320(-9.25,22.6) 321(-9.75,22.6) 322(-10.25,22.6) 323(-10.75,22.6) 324(-11.25,22.6) 325(-11.75,22.6) 326(-12.25,22.6) 327(-12.75,22.6) 328(-13.25,22.6) 329(-13.75,22.6) 330(-14.25,22.6) 331(-14.75,22.6) 332(-15.25,22.6) 333(-15.75,22.6) 334(-16.25,22.6) 335(-16.75,22.6) 336(-17.25,22.6) 337(-17.75,22.6) 338(-18.25,22.6) 339(-18.75,22.6) 340(-19.25,22.6) 341(-19.75,22.6) 342(-20.25,22.6) 343(-20.75,22.6) 344(-21.25,22.6)
Top Overlay:
  circle w0.25: c-23.96,21.25 r0.125
  lines w0.2: -21.4,-21.4 21.4,-21.4 21.4,21.4 -21.4,21.4 -21.4,-21.4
